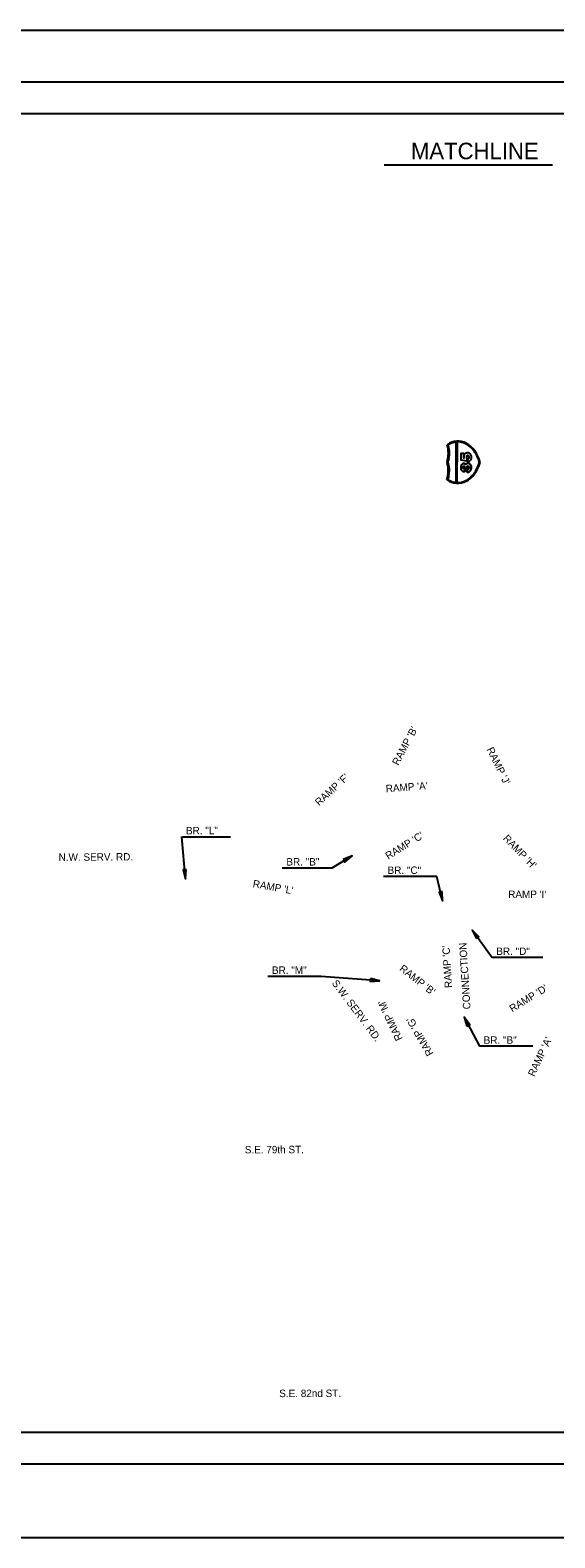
# Model space of a CAD drawing. Extents: x 2140911 to 2156666, y 139570 to 147689.
# Drawn here: x 2148478 to 2151304, y 139570 to 147689 of the extents above; entities that cross this region are included whole.
import ezdxf

# ---------------------------------------------------------------- set-up
doc = ezdxf.new("R2010")
doc.units = 0
for name, color, linetype in [('5', 7, 'Continuous'), ('7', 7, 'Continuous'), ('Default', 7, 'Continuous'), ('SHT_Match_Lines', 7, 'Continuous'), ('SHT_Plot_Shape_Full', 7, 'Continuous'), ('SHT_Plot_Shape_Half', 7, 'Continuous'), ('SHT_Sheet_Border', 7, 'Continuous'), ('ST-TEXT', 7, 'Continuous')]:
    doc.layers.add(name, color=color, linetype=linetype)

# ---------------------------------------------------------------- blocks, each defined once
blk = doc.blocks.new('ARROWHD')
at = {"layer": 'Default'}
blk.add_lwpolyline([(0.313, -0.054), (0.313, 0.052), (-0.005, -0.001)], close=True, dxfattribs=at)
blk = doc.blocks.new('i-35-shield')
at = {"layer": '7'}
blk.add_line((-18.5, 5.4), (18.4, 5.4), dxfattribs=at)
blk.add_line((-18.5, 5.4), (18.4, 5.4), dxfattribs=at)
for points in [[(-18.5, 4.7), (-18.5, 3.8), (-18.5, 3.2), (-18.5, 2.6), (-18.4, 1.5), (-18.2, 0.5), (-17.9, -0.4), (-17.6, -1.3), (-17.1, -2.5), (-16.6, -3.6), (-15.9, -4.9), (-15.1, -6.1), (-14.2, -7.2), (-13.3, -8.1), (-12.3, -9.1), (-11.8, -9.6), (-10.9, -10.4), (-10, -11.1), (-9, -11.7), (-7.8, -12.5), (-6.9, -13), (-5.7, -13.6), (-4.1, -14.4), (-3.1, -14.8), (-1.7, -15.3), (-0.8, -15.6), (0, -15.9), (0.7, -15.6), (1.7, -15.3), (3, -14.8), (4.1, -14.4), (5.7, -13.6), (6.9, -13), (7.8, -12.5), (9, -11.7), (9.9, -11.1), (10.8, -10.4), (11.7, -9.6), (12.3, -9.1), (13.3, -8.1), (14.1, -7.2), (15, -6.1), (15.8, -4.9), (16.6, -3.6), (17.1, -2.5), (17.6, -1.3), (17.9, -0.4), (18.1, 0.5), (18.3, 1.5), (18.5, 2.6), (18.5, 3.2), (18.5, 3.8), (18.5, 4.7), (-18.5, 4.7)], [(-8.9, -4.7), (-6.3, -4.7), (-6.3, -5.2), (-6.3, -5.4), (-6.2, -5.5), (-5.9, -5.9), (-5.5, -6.1), (-5.3, -6.2), (-5.1, -6.3), (-4.6, -6.3), (-4.2, -6.2), (-3.7, -5.8), (-3.5, -5.5), (-3.5, -5.1), (-3.8, -4.7), (-3.9, -4.6), (-4.2, -4.4), (-4.6, -4.3), (-5.8, -4.3), (-5.8, -2.6), (-4.6, -2.6), (-4.3, -2.6), (-4.1, -2.4), (-3.8, -2.1), (-3.7, -2), (-3.7, -1.6), (-3.9, -1.4), (-4.1, -1.2), (-4.3, -1.1), (-4.6, -1), (-5, -1), (-5.5, -1.2), (-5.7, -1.2), (-6, -1.5), (-6.1, -1.6), (-6.2, -2), (-6.2, -2.5), (-8.5, -2.5), (-8.5, -1.2), (-8.4, -0.8), (-8.2, -0.4), (-7.9, -0.1), (-7.2, 0.5), (-6.8, 0.7), (-6.1, 0.8), (-5.4, 0.9), (-4, 0.9), (-2.7, 0.6), (-2, 0.2), (-1.7, 0), (-1.5, -0.3), (-1.2, -0.8), (-1, -1.5), (-1, -1.9), (-1.3, -2.5), (-1.4, -2.7), (-1.6, -3), (-2, -3.3), (-2.1, -3.4), (-1.8, -3.5), (-1.5, -3.8), (-1.2, -4.2), (-0.9, -4.7), (-0.8, -5.1), (-0.8, -5.6), (-1.1, -6.4), (-1.3, -6.9), (-1.5, -7.2), (-2, -7.5), (-2.4, -7.7), (-2.9, -8), (-3.7, -8.2), (-4.7, -8.3), (-5.6, -8.3), (-6.9, -8), (-7.7, -7.5), (-8, -7.2), (-8.4, -6.9), (-8.6, -6.6), (-8.9, -5.8), (-8.9, -4.7)], [(3.8, -2.1), (4.1, -1.9), (4.7, -1.8), (5.7, -1.8), (6.2, -1.9), (6.7, -2), (7.1, -2.2), (7.6, -2.5), (7.9, -2.8), (8.3, -3.2), (8.5, -3.6), (8.7, -4), (8.9, -4.5), (8.9, -5.4), (8.7, -5.8), (8.5, -6.3), (8.3, -6.7), (7.9, -7), (7.5, -7.4), (6.9, -7.7), (6.3, -8), (5.7, -8.2), (4.9, -8.3), (4.2, -8.3), (3.6, -8.2), (2.9, -8), (2.4, -7.8), (1.8, -7.5), (1.2, -7.1), (0.8, -6.5), (0.5, -5.7), (0.5, -5.1), (2.9, -5.1), (3.1, -5.5), (3.4, -5.9), (3.6, -6.1), (4, -6.3), (4.2, -6.4), (4.9, -6.4), (5.1, -6.3), (5.6, -6.1), (5.9, -5.9), (6, -5.7), (6.1, -5.4), (6.1, -4.8), (6.1, -4.6), (5.9, -4.4), (5.6, -4.1), (5.1, -3.9), (4.9, -3.9), (4.2, -3.9), (4, -3.9), (3.8, -4), (3.6, -4.1), (3.4, -4.4), (0.9, -4.4), (2, 0.9), (8.3, 0.9), (8.3, -1.2), (4, -1.2), (3.8, -2.1)]]:
    blk.add_lwpolyline(points, dxfattribs=at)
for points in [[(-18.5, 4.7), (-18.5, 3.8), (-18.5, 3.2), (-18.5, 2.6), (-18.4, 1.5), (-18.2, 0.5), (-17.9, -0.4), (-17.6, -1.3), (-17.1, -2.5), (-16.6, -3.6), (-15.9, -4.9), (-15.1, -6.1), (-14.2, -7.2), (-13.3, -8.1), (-12.3, -9.1), (-11.8, -9.6), (-10.9, -10.4), (-10, -11.1), (-9, -11.7), (-7.8, -12.5), (-6.9, -13), (-5.7, -13.6), (-4.1, -14.4), (-3.1, -14.8), (-1.7, -15.3), (-0.8, -15.6), (0, -15.9), (0.7, -15.6), (1.7, -15.3), (3, -14.8), (4.1, -14.4), (5.7, -13.6), (6.9, -13), (7.8, -12.5), (9, -11.7), (9.9, -11.1), (10.8, -10.4), (11.7, -9.6), (12.3, -9.1), (13.3, -8.1), (14.1, -7.2), (15, -6.1), (15.8, -4.9), (16.6, -3.6), (17.1, -2.5), (17.6, -1.3), (17.9, -0.4), (18.1, 0.5), (18.3, 1.5), (18.5, 2.6), (18.5, 3.2), (18.5, 3.8), (18.5, 4.7)], [(-8.9, -5.8), (-8.6, -6.6), (-8.4, -6.9), (-8, -7.2), (-7.7, -7.5), (-6.9, -8), (-5.6, -8.3), (-4.7, -8.3), (-3.7, -8.2), (-2.9, -8), (-2.4, -7.7), (-2, -7.5), (-1.5, -7.2), (-1.3, -6.9), (-1.1, -6.4), (-0.8, -5.6), (-0.8, -5.1), (-0.9, -4.7), (-1.2, -4.2), (-1.5, -3.8), (-1.8, -3.5), (-2.1, -3.4), (-2, -3.3), (-1.6, -3), (-1.4, -2.7), (-1.3, -2.5), (-1, -1.9), (-1, -1.5), (-1.2, -0.8), (-1.5, -0.3), (-1.7, 0), (-2, 0.2), (-2.7, 0.6), (-4, 0.9), (-5.4, 0.9), (-6.1, 0.8), (-6.8, 0.7), (-7.2, 0.5), (-7.9, -0.1), (-8.2, -0.4), (-8.4, -0.8), (-8.5, -1.2), (-8.5, -2.5), (-6.2, -2.5), (-6.2, -2), (-6.1, -1.6), (-6, -1.5), (-5.7, -1.2), (-5.5, -1.2), (-5, -1), (-4.6, -1), (-4.3, -1.1), (-4.1, -1.2), (-3.9, -1.4), (-3.7, -1.6), (-3.7, -2), (-3.8, -2.1), (-4.1, -2.4), (-4.3, -2.6), (-4.6, -2.6), (-5.8, -2.6), (-5.8, -4.3), (-4.6, -4.3), (-4.2, -4.4), (-3.9, -4.6), (-3.8, -4.7), (-3.5, -5.1), (-3.5, -5.5), (-3.7, -5.8), (-4.2, -6.2), (-4.6, -6.3), (-5.1, -6.3), (-5.3, -6.2), (-5.5, -6.1), (-5.9, -5.9), (-6.2, -5.5), (-6.3, -5.4), (-6.3, -5.2), (-6.3, -4.7), (-8.9, -4.7)], [(3.8, -2.1), (4.1, -1.9), (4.7, -1.8), (5.7, -1.8), (6.2, -1.9), (6.7, -2), (7.1, -2.2), (7.6, -2.5), (7.9, -2.8), (8.3, -3.2), (8.5, -3.6), (8.7, -4), (8.9, -4.5), (8.9, -5.4), (8.7, -5.8), (8.5, -6.3), (8.3, -6.7), (7.9, -7), (7.5, -7.4), (6.9, -7.7), (6.3, -8), (5.7, -8.2), (4.9, -8.3), (4.2, -8.3), (3.6, -8.2), (2.9, -8), (2.4, -7.8), (1.8, -7.5), (1.2, -7.1), (0.8, -6.5), (0.5, -5.7), (0.5, -5.1), (2.9, -5.1), (3.1, -5.5), (3.4, -5.9), (3.6, -6.1), (4, -6.3), (4.2, -6.4), (4.9, -6.4), (5.1, -6.3), (5.6, -6.1), (5.9, -5.9), (6, -5.7), (6.1, -5.4), (6.1, -4.8), (6.1, -4.6), (5.9, -4.4), (5.6, -4.1), (5.1, -3.9), (4.9, -3.9), (4.2, -3.9), (4, -3.9), (3.8, -4), (3.6, -4.1), (3.4, -4.4), (0.9, -4.4), (2, 0.9), (8.3, 0.9), (8.3, -1.2), (4, -1.2)]]:
    blk.add_lwpolyline(points, close=True, dxfattribs=at)
for centre, major_axis, start_param, end_param in [((11.8, 3.9), (31, 0), 2.678593, 4.322471), ((-7.9, 27.7), (-21.2, 0), 1.177968, 1.951302), ((-11.8, 3.9), (-31, 0), 1.960714, 3.604592), ((7.8, 27.7), (21.2, 0), 4.331883, 5.105218)]:
    blk.add_ellipse(centre, major_axis=major_axis, ratio=0.713476, start_param=start_param, end_param=end_param, dxfattribs=at)
for points in [[(-15.7, 12.9), (-16.6, 11.5), (-17.4, 10), (-18.2, 7.4), (-18.4, 6.4), (-18.5, 5.4)], [(-15.7, 12.9), (-16.6, 11.5), (-17.4, 10), (-18.2, 7.4), (-18.4, 6.4), (-18.5, 5.4)], [(-15.7, 12.9), (-14.1, 12.5), (-12.5, 12.2), (-7.2, 11.7), (-3.5, 12), (0, 13)], [(0, 13), (-3.5, 12), (-7.2, 11.7), (-12.5, 12.2), (-14.1, 12.5), (-15.7, 12.9)], [(0, 13), (1.6, 12.5), (3.4, 12.2), (8.7, 11.7), (12.3, 12), (15.7, 12.9)], [(15.7, 12.9), (12.3, 12), (8.7, 11.7), (3.4, 12.2), (1.6, 12.5), (0, 13)], [(18.4, 5.4), (18.3, 6.3), (18.2, 7.2), (17.4, 9.7), (16.7, 11.4), (15.7, 12.9)], [(18.4, 5.4), (18.3, 6.3), (18.2, 7.2), (17.4, 9.7), (16.7, 11.4), (15.7, 12.9)]]:
    blk.add_open_spline(points, degree=3, dxfattribs=at)

msp = doc.modelspace()

# ---------------------------------------------------------------- linework, layer by layer
at = {"layer": '5'}
for p, q in [((2149315.1, 143119.2), (2149294.8, 143344.7)), ((2149294.8, 143344.7), (2149557.8, 143344.7)), ((2150668.9, 143131.5), (2150380.5, 143131.5)), ((2150699.7, 143001.2), (2150668.9, 143131.5)), ((2150860.3, 142842.3), (2150965.9, 142695.2)), ((2151240, 142695.2), (2150965.9, 142695.2)), ((2150046.3, 142593.3), (2149757.9, 142593.3)), ((2150359.4, 142569.4), (2150046.3, 142593.3)), ((2150816, 142373.2), (2150897.9, 142216.8)), ((2151186.3, 142216.8), (2150897.9, 142216.8))]:
    msp.add_line(p, q, dxfattribs=at)
msp.add_lwpolyline([(2150212.1, 143242.3), (2150103.5, 143176.7), (2149835.5, 143176.7)], dxfattribs=at)
at = {"layer": '7'}
msp.add_lwpolyline([(2150772.4, 145253.2), (2150776.5, 145252.9), (2150777.8, 145471.4), (2150773.7, 145471.1)], close=True, dxfattribs=at)
at = {"layer": 'SHT_Match_Lines'}
msp.add_line((2150384.6, 146963.2), (2151290.7, 146963.2), dxfattribs=at)
at = {"layer": 'SHT_Plot_Shape_Full'}
msp.add_lwpolyline([(2144487.6, 147688.9), (2156666.2, 147688.9), (2156666.2, 139569.8), (2144487.6, 139569.8)], close=True, dxfattribs=at)
at = {"layer": 'SHT_Plot_Shape_Half'}
msp.add_lwpolyline([(2145041.5, 147409.9), (2156543.6, 147409.9), (2156543.6, 139967.3), (2145041.5, 139967.3)], close=True, dxfattribs=at)
at = {"layer": 'SHT_Sheet_Border'}
msp.add_lwpolyline([(2156357.5, 140136.5), (2145701.2, 140136.5), (2145701.2, 147240.7), (2156357.5, 147240.7)], close=True, dxfattribs=at)

# ---------------------------------------------------------------- block references
at = {"layer": '5'}
for p, xscale, yscale, rotation in [((2150211.5, 143241.8), 157.48000000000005, 157.48000000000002, -148.84662943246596), ((2149315.1, 143119.2), 157.48, 157.48000000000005, 95.1629794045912), ((2150699.7, 143001.2), 157.48000000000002, 157.48000000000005, 103.30598438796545), ((2150860.3, 142842.3), 157.48000000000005, 157.48000000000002, -54.31882844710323), ((2150359.4, 142569.4), 157.48000000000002, 157.48000000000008, 175.60817608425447), ((2150816, 142373.2), 157.48000000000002, 157.48000000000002, -63.006684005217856)]:
    msp.add_blockref('ARROWHD', p, dxfattribs=dict(at, xscale=xscale, yscale=yscale, rotation=rotation))
at = {"layer": '7', "xscale": 5.905500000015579, "yscale": 5.905500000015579, "rotation": 89.67096440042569}
msp.add_blockref('i-35-shield', (2150804.7, 145362), dxfattribs=at)

# ---------------------------------------------------------------- texts
at = {"layer": 'SHT_Match_Lines'}
msp.add_text('MATCHLINE', height=89.02, dxfattribs=at).set_placement((2150529.1, 146993.8))
at = {"layer": 'ST-TEXT'}
for s, rotation, p in [("RAMP 'B'", 61.76126, (2150460.6, 143726.3)), ("RAMP 'J'", 295.91448, (2150935.7, 143815.8)), ("RAMP 'F'", 42.53524, (2150034.8, 143509.1)), ("RAMP 'A'", 4.29736, (2150395, 143584.3)), ('BR. "L"', 0.18941, (2149317.8, 143358.4)), ("RAMP 'C'", 31.65643, (2150406.9, 143221.2)), ("RAMP 'H'", 314.08986, (2151022.2, 143333.4)), ('N.W. SERV. RD.', 0.39436, (2148631.8, 143215.1)), ('BR. "B"', 360, (2149858.5, 143190.3)), ('BR. "C"', 360, (2150403.6, 143145.1)), ("RAMP 'L'", 349.78076, (2149675.1, 143074.5)), ("RAMP 'I'", 359.87569, (2151053, 143015.8)), ("RAMP 'C'", 93.51827, (2150751.2, 142532.1)), ('CONNECTION', 93.51827, (2150850.2, 142417.2)), ('BR. "D"', 360, (2150988.9, 142708.8)), ("RAMP 'B'", 321.83869, (2150463.6, 142628.6)), ('BR. "M"', 360, (2149781, 142607)), ('S.W. SERV. RD.', 306.98225, (2150100.7, 142556.3)), ("RAMP 'D'", 31.65643, (2151074.9, 142398.6)), ("RAMP 'M'", 115.23369, (2150485.3, 142257.9)), ("RAMP 'G'", 119.93158, (2150652.2, 142178.8)), ('BR. "B"', 360, (2150920.9, 142230.4)), ("RAMP 'A'", 64.74378, (2151193.6, 142050.5)), ('S.E. 79th ST.', 0.15793, (2149634.5, 141640.2)), ('S.E. 82nd ST.', 0.15793, (2149820, 140327.5))]:
    msp.add_text(s, height=40, rotation=rotation, dxfattribs=at).set_placement(p)

doc.saveas('drawing.dxf')
